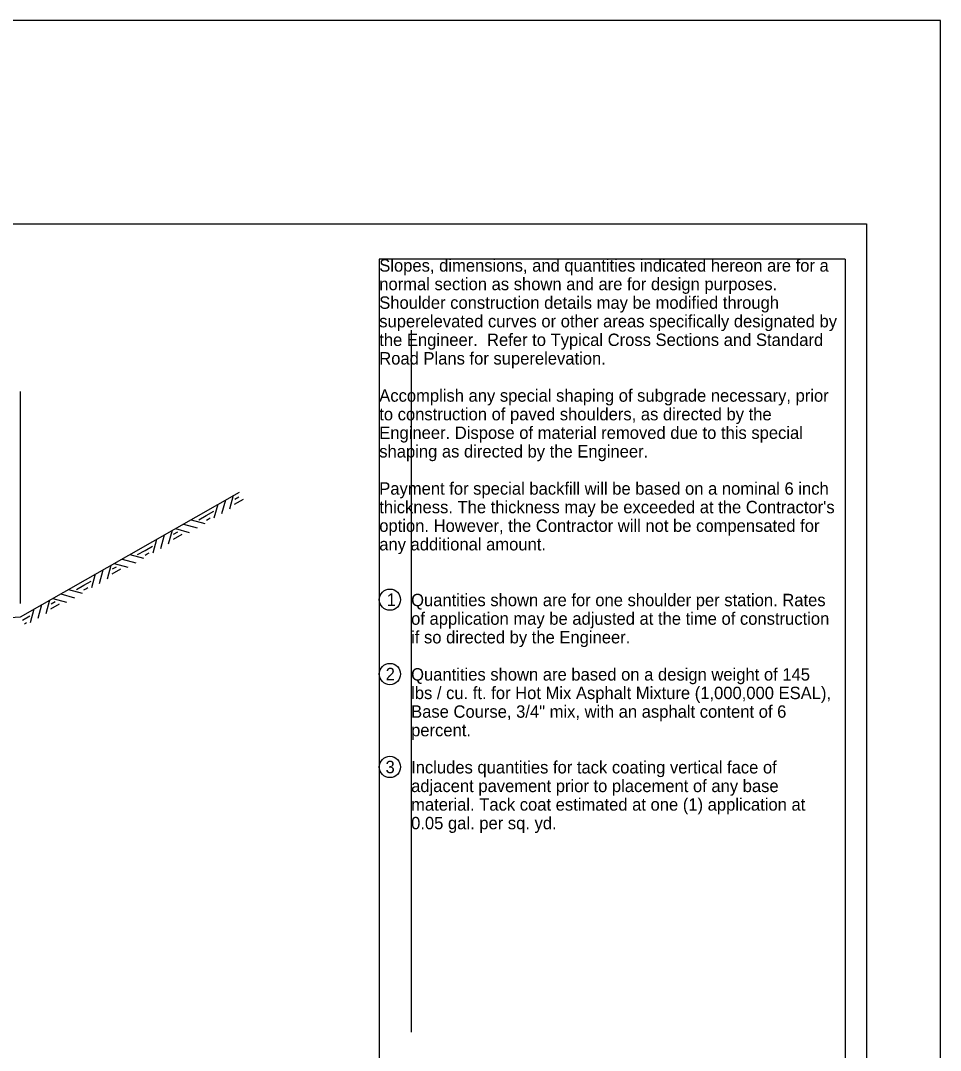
# Model space of a CAD drawing. Extents: x 10133 to 81668, y 2357 to 12713.
# Drawn here: x 12191 to 13490, y 5094 to 6548 of the extents above; entities that cross this region are included whole.
import ezdxf

# ---------------------------------------------------------------- set-up
doc = ezdxf.new("R2010")
doc.units = 0
for name, color, linetype in [('dsnNonPlotable', 7, 'Continuous'), ('dsnStdBorder', 7, 'Continuous'), ('dsnStdNameDate', 7, 'Continuous'), ('dsnStdNote', 7, 'Continuous'), ('SheetAddendum', 7, 'Continuous'), ('Text', 7, 'Continuous')]:
    doc.layers.add(name, color=color, linetype=linetype)

msp = doc.modelspace()

# ---------------------------------------------------------------- linework, layer by layer
at = {"layer": 'dsnNonPlotable'}
for p, q in [((12697.8, 6211.2), (12697.8, 4741.3)), ((13355.8, 6211.2), (12697.8, 6211.2)), ((13355.8, 6211.2), (13355.8, 4741.3)), ((12742.8, 6111.2), (12742.8, 5119.7))]:
    msp.add_line(p, q, dxfattribs=at)
at = {"layer": 'dsnStdBorder'}
msp.add_lwpolyline([(10250.8, 6261.2), (13385.8, 6261.2), (13385.8, 4251.2), (10250.8, 4251.2)], close=True, dxfattribs=at)
at = {"layer": 'dsnStdNameDate'}
msp.add_line((12191.3, 5725.2), (12191.3, 6024.4), dxfattribs=at)
at = {"layer": 'dsnStdNote'}
for centre in [(12712.8, 5730.4), (12712.8, 5625.4), (12712.8, 5494.2)]:
    msp.add_circle(centre, 15, dxfattribs=at)
at = {"layer": 'SheetAddendum'}
for p, q in [((12491.7, 5877.4), (12486.4, 5858.1)), ((12469.6, 5864.8), (12464.3, 5845.5)), ((12480.5, 5870.8), (12475.2, 5851.5)), ((12421.3, 5837.1), (12440.6, 5831.8)), ((12432, 5843.4), (12451.3, 5838.1)), ((12394, 5821.5), (12388.7, 5802.2)), ((12405.2, 5828.1), (12399.9, 5808.8)), ((12409.9, 5830.8), (12429.2, 5825.5)), ((12383.1, 5815.5), (12377.8, 5796.2)), ((12345.5, 5794.1), (12364.8, 5788.9)), ((12318.7, 5778.9), (12313.4, 5759.6)), ((12323.4, 5781.5), (12342.7, 5776.3)), ((12334.8, 5787.8), (12354.1, 5782.5)), ((12296.6, 5766.3), (12291.3, 5747)), ((12307.5, 5772.2), (12302.2, 5753)), ((12259, 5744.9), (12278.3, 5739.6)), ((12236.9, 5732.3), (12256.2, 5727)), ((12248.3, 5738.5), (12267.6, 5733.2)), ((12210.1, 5717), (12204.8, 5697.7)), ((12221, 5723), (12215.7, 5703.7)), ((12232.2, 5729.6), (12226.9, 5710.3))]:
    msp.add_line(p, q, dxfattribs=at)
for points in [[(12191.3, 5706.3), (12500.3, 5882.3)], [(12493.5, 5865.4), (12505.9, 5872.4)], [(12493.9, 5872.3), (12499.6, 5875.6)], [(12443.1, 5843.4), (12453.5, 5849.3)], [(12453.5, 5849.3), (12464, 5855.3)], [(12453.6, 5842.7), (12456.4, 5844.3)], [(12456.4, 5844.3), (12459.2, 5845.9)], [(12407, 5816.1), (12419.3, 5823.1)], [(12407.4, 5823.1), (12413.1, 5826.3)], [(12367, 5800.1), (12377.5, 5806)], [(12356.6, 5794.1), (12367, 5800.1)], [(12367, 5793.4), (12369.9, 5795)], [(12369.9, 5795), (12372.7, 5796.7)], [(12320.5, 5766.8), (12332.8, 5773.9)], [(12320.9, 5773.8), (12326.6, 5777)], [(12270, 5744.9), (12280.5, 5750.8)], [(12280.5, 5750.8), (12291, 5756.8)], [(12280.5, 5744.2), (12283.4, 5745.8)], [(12283.4, 5745.8), (12286.2, 5747.4)], [(12234, 5717.6), (12246.3, 5724.6)], [(12234.4, 5724.6), (12240.1, 5727.8)], [(11869.9, 5686), (12191.3, 5706.3)], [(12194, 5701.6), (12204.4, 5707.5)], [(12196.9, 5696.5), (12199.7, 5698.1)]]:
    msp.add_lwpolyline(points, dxfattribs=at)
at = {"layer": 'Text'}
msp.add_lwpolyline([(10146.3, 3964.2), (13490.3, 3964.2), (13490.3, 6548.2), (10146.3, 6548.2)], close=True, dxfattribs=at)

# ---------------------------------------------------------------- texts
at = {"layer": 'dsnStdNote'}
for s, p in [('Slopes, dimensions, and quantities indicated hereon are for a ', (12697.8, 6193.7)), ('normal section as shown and are for design purposes. ', (12697.8, 6167.5)), ('Shoulder construction details may be modified through ', (12697.8, 6141.2)), ('superelevated curves or other areas specifically designated by ', (12697.8, 6115)), ('the Engineer.  Refer to Typical Cross Sections and Standard ', (12697.8, 6088.7)), ('Road Plans for superelevation.', (12697.8, 6062.5)), ('Accomplish any special shaping of subgrade necessary, prior ', (12697.8, 6010)), ('to construction of paved shoulders, as directed by the ', (12697.8, 5983.7)), ('Engineer. Dispose of material removed due to this special ', (12697.8, 5957.5)), ('shaping as directed by the Engineer.', (12697.8, 5931.2)), ('Payment for special backfill will be based on a nominal 6 inch ', (12697.8, 5878.7)), ("thickness. The thickness may be exceeded at the Contractor's ", (12697.8, 5852.5)), ('option. However, the Contractor will not be compensated for ', (12697.8, 5826.2)), ('any additional amount.', (12697.8, 5800)), ('1', (12708.3, 5721.7)), ('Quantities shown are for one shoulder per station. Rates ', (12742.8, 5721.2)), ('of application may be adjusted at the time of construction ', (12742.8, 5695)), ('if so directed by the Engineer.', (12742.8, 5668.7)), ('2', (12706.9, 5616.7)), ('Quantities shown are based on a design weight of 145 ', (12742.8, 5616.2)), ('lbs / cu. ft. for Hot Mix Asphalt Mixture (1,000,000 ESAL), ', (12742.8, 5590)), ('Base Course, 3/4" mix, with an asphalt content of 6 ', (12742.8, 5563.7)), ('percent.', (12742.8, 5537.5)), ('3', (12706.7, 5485.4)), ('Includes quantities for tack coating vertical face of ', (12742.8, 5485)), ('adjacent pavement prior to placement of any base ', (12742.8, 5458.7)), ('material. Tack coat estimated at one (1) application at ', (12742.8, 5432.5)), ('0.05 gal. per sq. yd.', (12742.8, 5406.2))]:
    msp.add_text(s, height=17.5, dxfattribs=at).set_placement(p)

doc.saveas('drawing.dxf')
